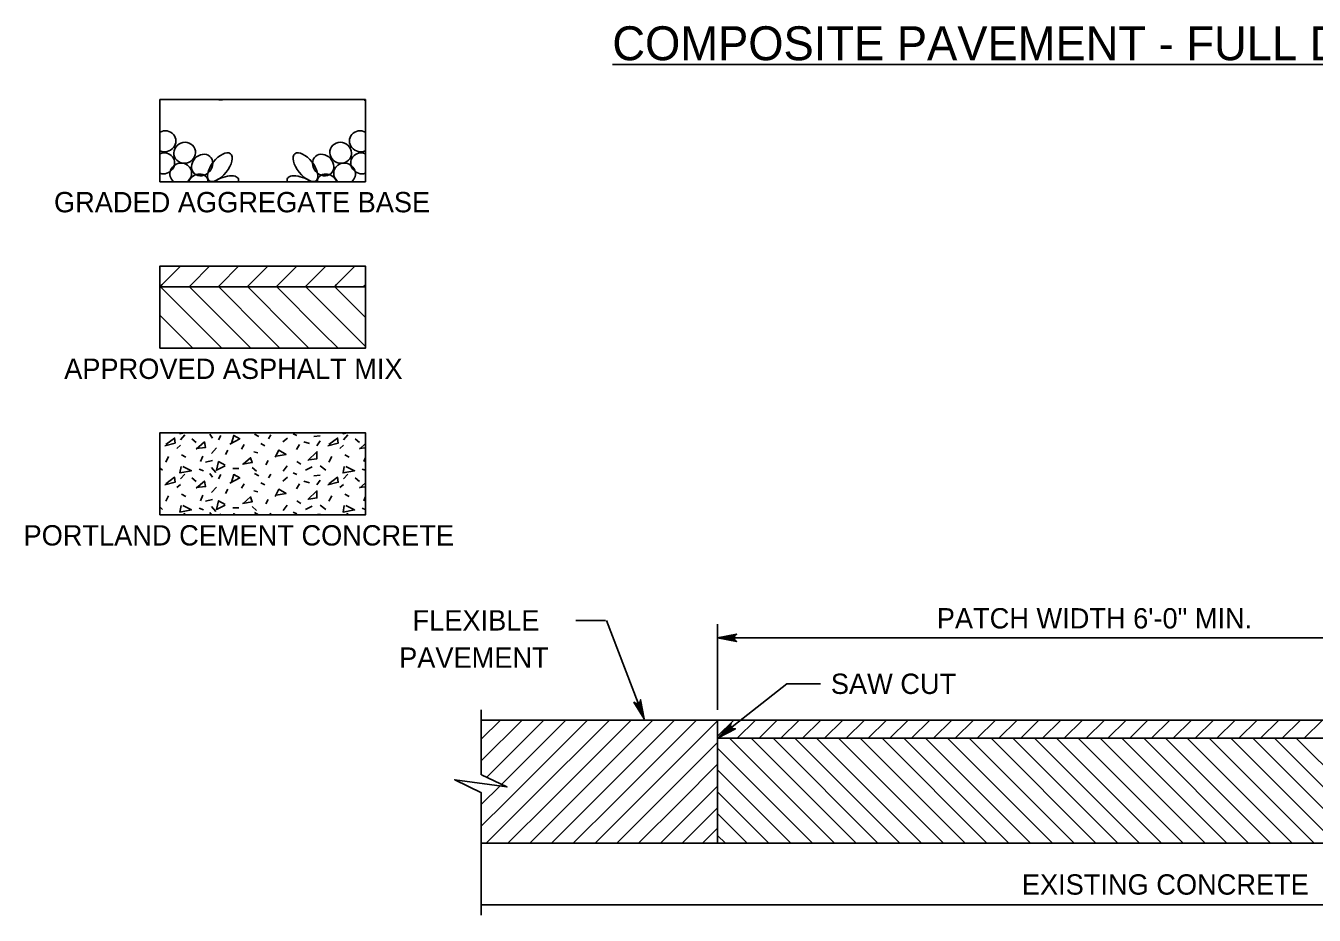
# Model space of a CAD drawing. Extents: x 3.47 to 10.73, y 1.11 to 10.92.
# Drawn here: x 3.525 to 7.328, y 5.67 to 8.293 of the extents above; entities that cross this region are included whole.
import ezdxf

# ---------------------------------------------------------------- set-up
doc = ezdxf.new("R2010")
doc.units = 0
for name, color, linetype in [('DETL-DIMS', 7, 'Continuous'), ('DETL-LINE', 7, 'Continuous'), ('DETL-NOTE', 7, 'Continuous'), ('DETL-PATT', 7, 'Continuous'), ('DETL-TITL', 7, 'Continuous')]:
    doc.layers.add(name, color=color, linetype=linetype)

msp = doc.modelspace()

# ---------------------------------------------------------------- linework, layer by layer
at = {"layer": 'DETL-DIMS'}
for p, q in [((5.2362, 6.5392), (5.1487, 6.5392)), ((5.2386, 6.5392), (5.35, 6.2487)), ((5.5666, 6.2756), (5.5666, 6.5283)), ((5.5666, 6.4877), (8.3545, 6.4877)), ((5.7714, 6.3521), (5.5686, 6.1929)), ((5.7713, 6.3521), (5.8708, 6.3521))]:
    msp.add_line(p, q, dxfattribs=at)
for points in [[(5.5666, 6.4877), (5.6231, 6.4983), (5.6188, 6.4953), (5.6165, 6.4915), (5.6159, 6.4877), (5.6165, 6.484), (5.6188, 6.4802), (5.6231, 6.4772), (5.5666, 6.4877), (5.6188, 6.4802), (5.6165, 6.484), (5.5666, 6.4877), (5.6159, 6.4877), (5.6165, 6.4915), (5.5666, 6.4877), (5.6188, 6.4953)], [(5.35, 6.2487), (5.3199, 6.2976), (5.3242, 6.2946), (5.3286, 6.2939), (5.3323, 6.2946), (5.3356, 6.2966), (5.3384, 6.3), (5.3396, 6.3052), (5.35, 6.2487), (5.3384, 6.3), (5.3356, 6.2966), (5.35, 6.2487), (5.3323, 6.2946), (5.3286, 6.2939), (5.35, 6.2487), (5.3242, 6.2946)], [(5.5686, 6.1929), (5.6065, 6.2361), (5.6049, 6.2311), (5.6055, 6.2267), (5.6073, 6.2233), (5.6102, 6.2208), (5.6143, 6.2192), (5.6196, 6.2195), (5.5686, 6.1929), (5.6143, 6.2192), (5.6102, 6.2208), (5.5686, 6.1929), (5.6073, 6.2233), (5.6055, 6.2267), (5.5686, 6.1929), (5.6049, 6.2311)]]:
    msp.add_lwpolyline(points, dxfattribs=at)
at = {"layer": 'DETL-LINE'}
for p, q in [((3.9213, 7.5233), (4.5274, 7.5233)), ((4.8696, 6.2756), (4.8696, 6.0839)), ((4.8696, 6.2453), (9.0515, 6.2453)), ((5.5666, 5.8817), (5.5666, 6.2453)), ((4.8696, 6.0306), (4.8696, 5.6696)), ((4.8696, 5.8817), (5.5666, 5.8817)), ((5.5666, 5.8817), (8.3545, 5.8817)), ((4.8696, 5.6999), (9.0515, 5.6999))]:
    msp.add_line(p, q, dxfattribs=at)
for points in [[(3.9213, 7.8329), (4.5274, 7.8329), (4.5274, 8.0753), (3.9213, 8.0753)], [(3.9213, 7.3415), (4.5274, 7.3415), (4.5274, 7.584), (3.9213, 7.584)], [(3.9213, 6.8502), (4.5274, 6.8502), (4.5274, 7.0926), (3.9213, 7.0926)], [(5.5666, 6.1914), (8.3545, 6.1914), (8.3545, 5.8817), (5.5666, 5.8817)]]:
    msp.add_lwpolyline(points, close=True, dxfattribs=at)
msp.add_lwpolyline([(4.8699, 6.0305), (4.7913, 6.0689), (4.9451, 6.048), (4.8699, 6.0838)], dxfattribs=at)
for centre, major_axis, ratio, start_param, end_param in [((4.0549, 8.1029), (0.0646, -0.0219), 0.282192, 5.340472, 5.835384), ((4.5099, 8.0543), (-0.0398, 0.0313), 0.479042, 4.647909, 4.773299)]:
    msp.add_ellipse(centre, major_axis=major_axis, ratio=ratio, start_param=start_param, end_param=end_param, dxfattribs=at)
at = {"layer": 'DETL-NOTE'}
msp.add_line((5.257, 8.1787), (8.682, 8.1787), dxfattribs=at)
at = {"layer": 'DETL-PATT'}
for p, q in [((3.9282, 7.5298), (3.9811, 7.5826)), ((4.0139, 7.5298), (4.0668, 7.5826)), ((4.0997, 7.5298), (4.1525, 7.5826)), ((4.1854, 7.5298), (4.2382, 7.5826)), ((4.2711, 7.5298), (4.3239, 7.5826)), ((4.3568, 7.5298), (4.4096, 7.5826)), ((4.4425, 7.5298), (4.4953, 7.5826)), ((3.9227, 7.5242), (3.9282, 7.5298)), ((4.0084, 7.5242), (4.0139, 7.5298)), ((4.0941, 7.5242), (4.0997, 7.5298)), ((4.1798, 7.5242), (4.1854, 7.5298)), ((4.2655, 7.5242), (4.2711, 7.5298)), ((4.3512, 7.5242), (4.3568, 7.5298)), ((4.4369, 7.5242), (4.4425, 7.5298)), ((4.0566, 7.3894), (3.9226, 7.5233)), ((4.1423, 7.3894), (4.0088, 7.5228)), ((4.228, 7.3894), (4.0946, 7.5228)), ((4.3137, 7.3894), (4.1803, 7.5228)), ((4.3994, 7.3894), (4.266, 7.5228)), ((4.4851, 7.3894), (4.3517, 7.5228)), ((4.5274, 7.4328), (4.4374, 7.5228)), ((4.5226, 7.5242), (4.5257, 7.5273)), ((3.9709, 7.3894), (3.9213, 7.4389)), ((4.0182, 7.3421), (3.9709, 7.3894)), ((4.1039, 7.3421), (4.0566, 7.3894)), ((4.1896, 7.3421), (4.1423, 7.3894)), ((4.2753, 7.3421), (4.228, 7.3894)), ((4.361, 7.3421), (4.3137, 7.3894)), ((4.4467, 7.3421), (4.3994, 7.3894)), ((4.5274, 7.3471), (4.4851, 7.3894)), ((3.9819, 7.0718), (3.9947, 7.0863)), ((4.0156, 7.075), (4.0284, 7.0638)), ((4.0685, 7.0879), (4.0766, 7.0766)), ((4.1006, 7.0847), (4.0942, 7.0718)), ((4.2001, 7.0879), (4.213, 7.0815)), ((4.2418, 7.075), (4.2483, 7.0863)), ((4.298, 7.0766), (4.2836, 7.0654)), ((4.314, 7.0895), (4.3253, 7.0847)), ((4.375, 7.0815), (4.3943, 7.0831)), ((4.4633, 7.0718), (4.4761, 7.0863)), ((4.497, 7.075), (4.5098, 7.0638)), ((3.9707, 7.0462), (3.9819, 7.0558)), ((4.0878, 7.0478), (4.0734, 7.0317)), ((4.1215, 7.0413), (4.1151, 7.0285)), ((4.1616, 7.0445), (4.1696, 7.0574)), ((4.1985, 7.0365), (4.2097, 7.0333)), ((4.2194, 7.0606), (4.2306, 7.0542)), ((4.3333, 7.0574), (4.3237, 7.0429)), ((4.3461, 7.0654), (4.3622, 7.0606)), ((4.3846, 7.0542), (4.3943, 7.0686)), ((4.452, 7.0462), (4.4633, 7.0558)), ((4.5268, 7.0593), (4.5098, 7.0445)), ((4.5098, 7.0462), (4.5268, 7.0481)), ((3.9386, 7.006), (3.9466, 7.0221)), ((3.9851, 7.0269), (3.9979, 7.0205)), ((4.0477, 7.0237), (4.0413, 7.0076)), ((4.0766, 7.0109), (4.0557, 7.006)), ((4.2338, 6.998), (4.2402, 7.0109)), ((4.3253, 7.0076), (4.3365, 6.9996)), ((4.4199, 7.006), (4.428, 7.0221)), ((4.4665, 7.0269), (4.4793, 7.0205)), ((4.5268, 7.018), (4.5226, 7.0076)), ((3.9224, 6.9872), (3.9289, 6.982)), ((3.9819, 6.9563), (3.9947, 6.9707)), ((4.0156, 6.9595), (4.0284, 6.9483)), ((4.0365, 6.9852), (4.0493, 6.9804)), ((4.0685, 6.9723), (4.0766, 6.9611)), ((4.0734, 6.99), (4.0862, 6.9756)), ((4.1006, 6.9691), (4.0942, 6.9563)), ((4.1359, 6.9868), (4.1536, 6.9868)), ((4.1937, 6.99), (4.2065, 6.9788)), ((4.2001, 6.9723), (4.213, 6.9659)), ((4.2418, 6.9595), (4.2483, 6.9707)), ((4.298, 6.9611), (4.2836, 6.9499)), ((4.2964, 6.9948), (4.2852, 6.9788)), ((4.314, 6.9739), (4.3253, 6.9691)), ((4.3702, 6.9916), (4.3509, 6.982)), ((4.375, 6.9659), (4.3943, 6.9675)), ((4.3943, 6.9948), (4.4103, 6.982)), ((4.4633, 6.9563), (4.4761, 6.9707)), ((4.497, 6.9595), (4.5098, 6.9483)), ((4.5178, 6.9852), (4.5268, 6.9818)), ((3.9707, 6.9306), (3.9819, 6.9402)), ((4.0878, 6.9322), (4.0734, 6.9162)), ((4.1215, 6.9258), (4.1151, 6.913)), ((4.1616, 6.929), (4.1696, 6.9419)), ((4.1985, 6.921), (4.2097, 6.9178)), ((4.2194, 6.9451), (4.2306, 6.9386)), ((4.3333, 6.9419), (4.3237, 6.9274)), ((4.3461, 6.9499), (4.3622, 6.9451)), ((4.3846, 6.9386), (4.3943, 6.9531)), ((4.452, 6.9306), (4.4633, 6.9402)), ((4.5268, 6.9437), (4.5098, 6.929)), ((4.5098, 6.9306), (4.5268, 6.9326)), ((3.9386, 6.8905), (3.9466, 6.9066)), ((3.9851, 6.9114), (3.9979, 6.9049)), ((4.0477, 6.9082), (4.0413, 6.8921)), ((4.0766, 6.8953), (4.0557, 6.8905)), ((4.2338, 6.8825), (4.2402, 6.8953)), ((4.3253, 6.8921), (4.3365, 6.8841)), ((4.4199, 6.8905), (4.428, 6.9066)), ((4.4665, 6.9114), (4.4793, 6.9049)), ((4.5268, 6.9024), (4.5226, 6.8921)), ((3.9224, 6.8717), (3.9289, 6.8664)), ((3.9907, 6.8507), (3.9947, 6.8552)), ((4.0365, 6.8696), (4.0493, 6.8648)), ((4.0685, 6.8568), (4.0729, 6.8507)), ((4.0734, 6.8745), (4.0862, 6.86)), ((4.1006, 6.8536), (4.0992, 6.8507)), ((4.1359, 6.8713), (4.1536, 6.8713)), ((4.1937, 6.8745), (4.2065, 6.8632)), ((4.2001, 6.8568), (4.2124, 6.8507)), ((4.2457, 6.8507), (4.2483, 6.8552)), ((4.2964, 6.8793), (4.2852, 6.8632)), ((4.314, 6.8584), (4.3253, 6.8536)), ((4.3702, 6.8761), (4.3509, 6.8664)), ((4.3786, 6.8507), (4.3943, 6.852)), ((4.3943, 6.8793), (4.4103, 6.8664)), ((4.4721, 6.8507), (4.4761, 6.8552)), ((4.5178, 6.8696), (4.5268, 6.8663)), ((4.8696, 6.189), (4.926, 6.2453)), ((4.8696, 6.1247), (4.9903, 6.2453)), ((4.8856, 6.0763), (5.0545, 6.2453)), ((4.9287, 6.0552), (5.1188, 6.2453)), ((4.942, 6.0042), (5.1831, 6.2453)), ((5.0063, 6.0042), (5.2474, 6.2453)), ((5.2634, 6.1971), (5.3117, 6.2453)), ((5.2634, 6.1328), (5.376, 6.2453)), ((5.2634, 6.0685), (5.4402, 6.2453)), ((5.2634, 6.0042), (5.5045, 6.2453)), ((5.3277, 6.0042), (5.5688, 6.2453)), ((5.5666, 6.1975), (5.6145, 6.2453)), ((5.6249, 6.1914), (5.6788, 6.2453)), ((5.6892, 6.1914), (5.7431, 6.2453)), ((5.7536, 6.1914), (5.8075, 6.2453)), ((5.8179, 6.1914), (5.8718, 6.2453)), ((5.8823, 6.1914), (5.9362, 6.2453)), ((5.9466, 6.1914), (6.0005, 6.2453)), ((6.011, 6.1914), (6.0649, 6.2453)), ((6.0753, 6.1914), (6.1292, 6.2453)), ((6.1396, 6.1914), (6.1936, 6.2453)), ((6.204, 6.1914), (6.2579, 6.2453)), ((6.2683, 6.1914), (6.3223, 6.2453)), ((6.3327, 6.1914), (6.3866, 6.2453)), ((6.397, 6.1914), (6.451, 6.2453)), ((6.4614, 6.1914), (6.5153, 6.2453)), ((6.5257, 6.1914), (6.5797, 6.2453)), ((6.5901, 6.1914), (6.644, 6.2453)), ((6.6544, 6.1914), (6.7083, 6.2453)), ((6.7188, 6.1914), (6.7727, 6.2453)), ((6.7831, 6.1914), (6.837, 6.2453)), ((6.8475, 6.1914), (6.9014, 6.2453)), ((6.9118, 6.1914), (6.9657, 6.2453)), ((6.9762, 6.1914), (7.0301, 6.2453)), ((7.0405, 6.1914), (7.0944, 6.2453)), ((7.1048, 6.1914), (7.1588, 6.2453)), ((7.1692, 6.1914), (7.2231, 6.2453)), ((7.2335, 6.1914), (7.2875, 6.2453)), ((7.2979, 6.1914), (7.3518, 6.2453)), ((5.0706, 6.0042), (5.2634, 6.1971)), ((5.392, 6.0042), (5.5666, 6.1789)), ((5.5666, 6.1914), (8.3545, 6.1914)), ((5.5666, 6.1622), (5.8471, 5.8817)), ((5.6018, 6.1914), (5.9115, 5.8817)), ((5.6661, 6.1914), (5.9758, 5.8817)), ((5.7305, 6.1914), (6.0402, 5.8817)), ((5.7948, 6.1914), (6.1045, 5.8817)), ((5.8592, 6.1914), (6.1689, 5.8817)), ((5.9235, 6.1914), (6.2332, 5.8817)), ((5.9879, 6.1914), (6.2976, 5.8817)), ((6.0522, 6.1914), (6.3619, 5.8817)), ((6.1166, 6.1914), (6.4263, 5.8817)), ((6.1809, 6.1914), (6.4906, 5.8817)), ((6.2452, 6.1914), (6.555, 5.8817)), ((6.3096, 6.1914), (6.6193, 5.8817)), ((6.3739, 6.1914), (6.6836, 5.8817)), ((6.4383, 6.1914), (6.748, 5.8817)), ((6.5026, 6.1914), (6.8123, 5.8817)), ((6.567, 6.1914), (6.8767, 5.8817)), ((6.6313, 6.1914), (6.941, 5.8817)), ((6.6957, 6.1914), (7.0054, 5.8817)), ((6.76, 6.1914), (7.0697, 5.8817)), ((6.8244, 6.1914), (7.1341, 5.8817)), ((6.8887, 6.1914), (7.1984, 5.8817)), ((6.9531, 6.1914), (7.2628, 5.8817)), ((7.0174, 6.1914), (7.3271, 5.8817)), ((7.0818, 6.1914), (7.3915, 5.8817)), ((7.1461, 6.1914), (7.4558, 5.8817)), ((7.2104, 6.1914), (7.5202, 5.8817)), ((7.2748, 6.1914), (7.5845, 5.8817)), ((5.1348, 6.0042), (5.2634, 6.1328)), ((5.4563, 6.0042), (5.5666, 6.1146)), ((5.5666, 6.0979), (5.7828, 5.8817)), ((4.8696, 5.9961), (4.9259, 6.0524)), ((5.1991, 6.0042), (5.2634, 6.0685)), ((5.5205, 6.0042), (5.5666, 6.0503)), ((5.5666, 6.0335), (5.7184, 5.8817)), ((4.8696, 5.9319), (4.942, 6.0042)), ((4.8838, 5.8817), (5.0063, 6.0042)), ((4.948, 5.8817), (5.0706, 6.0042)), ((5.0134, 5.8827), (5.1348, 6.0042)), ((5.0766, 5.8817), (5.1991, 6.0042)), ((5.1409, 5.8817), (5.2634, 6.0042)), ((5.2634, 5.9399), (5.3277, 6.0042)), ((5.2694, 5.8817), (5.392, 6.0042)), ((5.3337, 5.8817), (5.4563, 6.0042)), ((5.398, 5.8817), (5.5205, 6.0042)), ((5.4623, 5.8817), (5.5656, 5.985)), ((5.2052, 5.8817), (5.2634, 5.9399)), ((5.5666, 5.9692), (5.6541, 5.8817)), ((5.5213, 5.8808), (5.5674, 5.9269)), ((5.5666, 5.9048), (5.5898, 5.8817))]:
    msp.add_line(p, q, dxfattribs=at)
for points in [[(3.9354, 7.0542), (3.9658, 7.0622), (3.9642, 7.0766), (3.9386, 7.0574)], [(3.9806, 7.0911), (3.9803, 7.0895), (3.9887, 7.0911)], [(4.1279, 7.059), (4.1568, 7.075), (4.1391, 7.0847), (4.1327, 7.0622)], [(4.4167, 7.0542), (4.4472, 7.0622), (4.4456, 7.0766), (4.4199, 7.0574)], [(4.4619, 7.0911), (4.4617, 7.0895), (4.47, 7.0911)], [(4.0284, 7.0462), (4.0557, 7.0494), (4.0525, 7.0654), (4.0284, 7.0445)], [(4.2611, 7.0205), (4.2723, 7.0413), (4.2932, 7.0285), (4.2643, 7.0237)], [(4.3606, 7.0125), (4.3846, 7.0157), (4.3846, 7.0365), (4.3574, 7.0109)], [(4.1135, 6.9948), (4.0878, 6.982), (4.0942, 7.0076), (4.1135, 6.9964)], [(4.1648, 6.9996), (4.1937, 7.0044), (4.1889, 7.0189), (4.1664, 6.9996)], [(3.9354, 6.9386), (3.9658, 6.9467), (3.9642, 6.9611), (3.9386, 6.9419)], [(3.9835, 6.9932), (3.9803, 6.9739), (4.014, 6.9804), (3.9883, 6.9932)], [(4.1279, 6.9435), (4.1568, 6.9595), (4.1391, 6.9691), (4.1327, 6.9467)], [(4.4167, 6.9386), (4.4472, 6.9467), (4.4456, 6.9611), (4.4199, 6.9419)], [(4.4649, 6.9932), (4.4617, 6.9739), (4.4954, 6.9804), (4.4697, 6.9932)], [(4.0284, 6.9306), (4.0557, 6.9338), (4.0525, 6.9499), (4.0284, 6.929)], [(4.2611, 6.9049), (4.2723, 6.9258), (4.2932, 6.913), (4.2643, 6.9082)], [(4.3606, 6.8969), (4.3846, 6.9001), (4.3846, 6.921), (4.3574, 6.8953)], [(4.1135, 6.8793), (4.0878, 6.8664), (4.0942, 6.8921), (4.1135, 6.8809)], [(4.1648, 6.8841), (4.1937, 6.8889), (4.1889, 6.9033), (4.1664, 6.8841)], [(3.9835, 6.8777), (3.9803, 6.8584), (4.014, 6.8648), (3.9883, 6.8777)], [(4.1445, 6.8507), (4.1391, 6.8536), (4.1383, 6.8507)], [(4.4649, 6.8777), (4.4617, 6.8584), (4.4954, 6.8648), (4.4697, 6.8777)]]:
    msp.add_lwpolyline(points, dxfattribs=at)
for centre, major_axis, ratio, start_param, end_param in [((3.9361, 7.952), (0.03, 0.012), 0.948581, 3.86971, 7.971447), ((4.5126, 7.952), (-0.03, 0.012), 0.948581, 4.594923, 8.696661), ((3.9325, 7.887), (0.03, 0.012), 0.948581, 3.994159, 7.846998), ((4.5162, 7.887), (-0.03, 0.012), 0.948581, 4.719373, 8.572212), ((3.9826, 7.8569), (0.03, 0.012), 0.948581, 4.992896, 9.917049), ((4.4661, 7.8569), (-0.03, 0.012), 0.948581, 2.649322, 7.573475), ((4.033, 7.8233), (0.0227, 0.0256), 0.844245, 5.660134, 8.193891), ((4.1056, 7.8223), (-0.0464, -0.0197), 0.422273, 2.743765, 5.105587), ((4.3432, 7.8223), (0.0464, -0.0197), 0.422273, 1.177599, 3.53942), ((4.4157, 7.8233), (-0.0227, 0.0256), 0.844245, 4.37248, 6.906237)]:
    msp.add_ellipse(centre, major_axis=major_axis, ratio=ratio, start_param=start_param, end_param=end_param, dxfattribs=at)
for centre, major_axis, ratio in [((3.9942, 7.9182), (0.03, 0.012), 0.948581), ((4.4545, 7.9182), (-0.03, 0.012), 0.948581), ((4.0457, 7.8819), (0.0227, 0.0256), 0.844245), ((4.0978, 7.8757), (-0.0313, -0.0398), 0.479042), ((4.3509, 7.8757), (0.0313, -0.0398), 0.479042), ((4.403, 7.8819), (-0.0227, 0.0256), 0.844245)]:
    msp.add_ellipse(centre, major_axis=major_axis, ratio=ratio, dxfattribs=at)

# ---------------------------------------------------------------- texts
at = {"layer": 'DETL-NOTE'}
for s, p in [('GRADED AGGREGATE BASE', (3.6085, 7.7426)), ('APPROVED ASPHALT MIX', (3.6386, 7.2512)), ('PORTLAND CEMENT CONCRETE', (3.5186, 6.7599)), ('FLEXIBLE', (4.6668, 6.5092)), ('PATCH WIDTH 6\'-0" MIN.', (6.2138, 6.5152)), (' PAVEMENT', (4.6048, 6.3992)), ('SAW CUT', (5.9011, 6.3221)), ('EXISTING CONCRETE', (6.4648, 5.7302))]:
    msp.add_text(s, height=0.06, dxfattribs=at).set_placement(p)
at = {"layer": 'DETL-TITL'}
msp.add_text('COMPOSITE PAVEMENT - FULL DEPTH PATCH', height=0.1, dxfattribs=at).set_placement((5.2563, 8.1912))

doc.saveas('drawing.dxf')
